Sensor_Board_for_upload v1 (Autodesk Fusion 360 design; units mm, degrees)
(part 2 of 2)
sketch "Sketch7" plane through (-0.0036, 0, 0) normal (-1, 0, 0) x axis (0, -1, 0)
  line L1 (131.7809, -1.8584) -> (65.0417, -1.8584)
  line L2 (135.78, -1.8416) -> (131.7809, -1.8584)
  line L3 (135.7809, 0.1416) -> (135.78, -1.8416)
  line L4 (131.7809, 0.1416) -> (135.7809, 0.1416)
  line L5 (131.7809, 7.5) -> (131.7809, 0.1416)
  line L6 (117.7809, 7.5) -> (131.7809, 7.5)
  line L7 (117.7809, 13.1283) -> (117.7809, 7.5)
  line L8 (110.4051, 13.1776) -> (117.7809, 13.1283)
  line L9 (110.3917, 11.1776) -> (110.4051, 13.1776)
  line L10 (115.7809, 11.1416) -> (110.3917, 11.1776)
  line L11 (115.7809, 5.5) -> (115.7809, 11.1416)
  line L12 (129.7809, 5.5) -> (115.7809, 5.5)
  line L13 (129.7809, 0.1416) -> (129.7809, 5.5)
  line L14 (71.0417, 0.1416) -> (129.7809, 0.1416)
  line L15 (71.0417, 10) -> (71.0417, 0.1416)
  line L16 (88.9317, 10.0211) -> (71.0417, 10)
  line L17 (88.9293, 12.0211) -> (88.9317, 10.0211)
  line L18 (69.0417, 11.9976) -> (88.9293, 12.0211)
  line L19 (69.0417, 0.319) -> (69.0417, 11.9976)
  line L20 (65.0417, 0.319) -> (69.0417, 0.319)
  line L21 (65.0417, -1.8584) -> (65.0417, 0.319)
  line L22 (65.0417, -1.8584) -> (135.78, -1.8416)
  line L23 (69.0417, 0.319) -> (65.0417, 0.319)
  line L24 (131.7809, 11.9976) -> (69.0417, 11.9976)
  line L25 (131.7809, 0.1416) -> (131.7809, 11.9976)
  line L26 (69.0417, 0.1416) -> (131.7809, 0.1416)
  line L27 (69.0417, 11.9976) -> (69.0417, 0.1416)
  point P4 (135.78, -1.8416)
  point P23 (135.78, -1.8416)
  point P2 (65.0417, -1.8584)
  point P24 (65.0417, -1.8584)
  point P22 (65.0417, 0.319)
  point P25 (65.0417, 0.319)
  point P21 (69.0417, 0.319)
  point P26 (69.0417, 0.319)
  point P6 (131.7809, 0.1416)
  point P29 (131.7809, 0.1416)
  point P20 (69.0417, 11.9976)
  point P27 (69.0417, 11.9976)
  coincident P4 P23
  coincident P2 P24
  coincident P22 P25
  coincident P21 P26
  horizontal L24
  vertical L25
  horizontal L26
  vertical L27
  coincident P6 P29
  coincident P20 P27
extrude "Extrude8" new body sketch "Sketch7" profile of L5 L6 L7 L9 L10 L11 L12 L13 L14 L15 L16 L17 L19 L24 L25 L26 L27 along normal blind 2
extrude "Extrude9" new body of existing geometry blind 2
extrude "Extrude10" new body of existing geometry blind 2
position "Position2"
extrude "Extrude11" new body of existing geometry blind 2
extrude "Extrude12" new body of existing geometry blind 2
extrude "Extrude13" new body of existing geometry blind 2
combine "Combine2"
extrude "Extrude14" new body of existing geometry to an object bodies "Left_lid"
combine "Combine3"
sketch "Sketch8" plane through (45.9964, 0, 0) normal (1, 0, 0) x axis (0, 1, 0)
  line L1 (-99.0604, 13.5068) -> (-99.0604, 12.0068)
  line L2 (-102.3675, 13.5022) -> (-99.0604, 13.5068)
  line L3 (-95.2322, 22.0057) -> (-102.3675, 13.5022)
  line L4 (-90.4314, 22.0057) -> (-95.2322, 22.0057)
  line L5 (-90.4296, 13.519) -> (-90.4314, 22.0057)
  line L6 (-90.4296, 10.0045) -> (-90.4296, 13.519)
  line L7 (-88.9317, 10) -> (-90.4296, 10.0045)
  line L8 (-88.9317, 11.9976) -> (-88.9317, 10)
  line L9 (-88.9374, 11.9976) -> (-88.9317, 11.9976)
  line L10 (-88.9374, 12.0211) -> (-88.9374, 11.9976)
  line L11 (-88.9317, 12.0211) -> (-88.9374, 12.0211)
  line L12 (-88.9317, 23.5057) -> (-88.9317, 12.0211)
  line L13 (-95.9317, 23.5057) -> (-88.9317, 23.5057)
  line L14 (-104.6394, 13.1283) -> (-95.9317, 23.5057)
  line L15 (-110.3917, 13.1283) -> (-104.6394, 13.1283)
  line L16 (-110.3917, 11.1776) -> (-110.3917, 13.1283)
  line L17 (-110.4051, 11.1776) -> (-110.3917, 11.1776)
  line L18 (-110.4051, 13.1283) -> (-110.4051, 11.1776)
  line L19 (-117.7809, 13.1283) -> (-110.4051, 13.1283)
  line L20 (-117.7809, 7.5) -> (-117.7809, 13.1283)
  line L21 (-131.7809, 7.5) -> (-117.7809, 7.5)
  line L22 (-131.7809, 0.1416) -> (-131.7809, 7.5)
  line L23 (-135.7809, 0.1416) -> (-131.7809, 0.1416)
  line L24 (-135.78, -1.8416) -> (-135.7809, 0.1416)
  line L25 (-131.7809, -1.8584) -> (-135.78, -1.8416)
  line L26 (-65.0417, -1.8584) -> (-131.7809, -1.8584)
  line L27 (-65.0417, 0.319) -> (-65.0417, -1.8584)
  line L28 (-69.0417, 0.319) -> (-65.0417, 0.319)
  line L29 (-69.0417, 11.9976) -> (-69.0417, 0.319)
  line L30 (-88.9293, 11.9976) -> (-69.0417, 11.9976)
  line L31 (-88.9317, 10.0211) -> (-88.9293, 11.9976)
  line L32 (-71.0417, 10) -> (-88.9317, 10.0211)
  line L33 (-71.0417, 0.1416) -> (-71.0417, 10)
  line L34 (-129.7809, 0.1416) -> (-71.0417, 0.1416)
  line L35 (-129.7809, 5.5) -> (-129.7809, 0.1416)
  line L36 (-115.7809, 5.5) -> (-129.7809, 5.5)
  line L37 (-115.7809, 8.2745) -> (-115.7809, 5.5)
  line L38 (-99.0604, 8.2745) -> (-115.7809, 8.2745)
  line L39 (-99.0604, 11.9976) -> (-99.0604, 8.2745)
  line L40 (-105.5881, 11.9976) -> (-99.0604, 11.9976)
  line L41 (-99.0604, 12.0068) -> (-105.5881, 11.9976)
  line L42 (-95.9317, 23.5057) -> (-104.6394, 13.1283)
  line L43 (-88.9293, 11.9976) -> (-88.9317, 23.5057)
  line L44 (-69.0417, 0.319) -> (-69.0417, 11.9976)
  line L45 (-69.0417, -1.8584) -> (-69.0417, 0.319)
  line L46 (-131.7809, 7.5) -> (-131.7809, -1.8584)
  line L47 (-117.7809, 13.1283) -> (-117.7809, 7.5)
  line L48 (-125.7809, 7.5) -> (-131.7809, 7.5)
  line L49 (-125.7809, -1.8584) -> (-125.7809, 7.5)
  line L50 (-131.7809, -1.8584) -> (-125.7809, -1.8584)
  line L51 (-131.7809, 7.5) -> (-131.7809, -1.8584)
  line L52 (-117.7809, 7.5) -> (-131.7809, 7.5)
  line L53 (-117.7809, 9.5) -> (-117.7809, 7.5)
  line L54 (-131.7809, 9.5) -> (-117.7809, 9.5)
  line L55 (-131.7809, 7.5) -> (-131.7809, 9.5)
  line L56 (-69, 11.9976) -> (-88.9293, 11.9976)
  line L57 (-69, 14) -> (-69, 11.9976)
  line L58 (-88.9293, 14) -> (-69, 14)
  line L59 (-88.9293, 11.9976) -> (-88.9293, 14)
  line L60 (-88.9317, 10) -> (-99.0604, 10.1361)
  circle C1 centre (-114.9874, 10.6426) radius 1
  point P17 (-104.6394, 13.1283)
  point P44 (-104.6394, 13.1283)
  point P16 (-95.9317, 23.5057)
  point P45 (-95.9317, 23.5057)
  point P15 (-88.9317, 23.5057)
  point P46 (-88.9317, 23.5057)
  point P33 (-88.9293, 11.9976)
  point P47 (-88.9293, 11.9976)
  point P32 (-69.0417, 11.9976)
  point P48 (-69.0417, 11.9976)
  point P31 (-69.0417, 0.319)
  point P49 (-69.0417, 0.319)
  point P50 (-69.0417, -1.8584)
  point P28 (-131.7809, -1.8584)
  point P51 (-131.7809, -1.8584)
  point P24 (-131.7809, 7.5)
  point P52 (-131.7809, 7.5)
  point P23 (-117.7809, 7.5)
  point P53 (-117.7809, 7.5)
  point P22 (-117.7809, 13.1283)
  point P54 (-117.7809, 13.1283)
  point P56 (-125.7809, -1.8584)
  point P64 (-99.0604, 10.1361)
  point P10 (-88.9317, 10)
  point P65 (-88.9317, 10)
  point P55 (-125.7809, 7.5)
  point P60 (-131.7809, 9.5)
  coincident P17 P44
  coincident P16 P45
  coincident P15 P46
  coincident P33 P47
  coincident P32 P48
  coincident P31 P49
  coincident L26 P50
  perpendicular L26 L45
  coincident P28 P51
  coincident P24 P52
  coincident P23 P53
  coincident P22 P54
  horizontal L48
  vertical L49
  horizontal L50
  vertical L51
  coincident L26 P56
  horizontal L52
  vertical L53
  horizontal L54
  vertical L55
  horizontal L56
  vertical L57
  horizontal L58
  vertical L59
  midpoint L39 P64
  coincident P10 P65
  dimension "d233" distance P52 P55 = 6
  dimension "d234" distance P52 P60 = 2
extrude "Extrude15" new body sketch "Sketch8" profile of C1 L1 L2 L3 L4 L5 L6 L8 L9 L10 L11 L12 L13 L14 L15 L16 L17 L18 L19 L20 L21 L22 L26 L29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 along normal blind 2 bodies "Right_lid"
extrude "Extrude16" new body sketch "Sketch8" profile of L30 L56 L57 L58 L59 against normal blind 2
extrude "Extrude17" add of existing geometry blind 2
extrude "Extrude18" new body of existing geometry blind 2
extrude "Extrude19" add of existing geometry blind 2
extrude "Extrude20" add of existing geometry blind 6
extrude "Extrude21" add of existing geometry blind 2
extrude "Extrude22" add of existing geometry to an object
extrude "Extrude23" add of existing geometry blind 0.775
remove_body "RemoveBody1"
remove_body "RemoveBody2"
remove_instance "RemoveInstance1"
remove_instance "RemoveInstance1"
remove_instance "RemoveInstance2"
remove_instance "RemoveInstance3"
remove_instance "RemoveInstance4"
remove_instance "RemoveInstance5"
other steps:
extrude "Extrude1" cut sketch "Sketch7" profile of L1 L2 L3 L4 L11 L12 L10 L9 against normal blind 11
extrude "Extrude1" cut sketch "Sketch7" profile of L1 L2 L3 L4 L11 L12 L10 L9 against normal blind 11
extrude "Extrude1" cut sketch "Sketch1" profile of L4 C1 C2 C3 L8 L17 L29 L30 L31 L32 along normal blind 10
extrude "Extrude1" cut sketch "Sketch1" profile of L4 C1 C2 C3 L8 L17 L29 L30 L31 L32 along normal blind 10
extrude "Extrude1" cut sketch "Sketch1" profile of L4 C1 C2 C3 L8 L17 L29 L30 L31 L32 along normal blind 10
extrude "Extrude1" cut sketch "Sketch1" profile of L4 C1 C2 C3 L8 L17 L29 L30 L31 L32 along normal blind 10
extrude "Extrude1" cut sketch "Sketch7" profile of L1 L2 L3 L4 L11 L12 L10 L9 against normal blind 11
extrude "Extrude1" cut sketch "Sketch7" profile of L1 L2 L3 L4 L11 L12 L10 L9 against normal blind 11
extrude "Extrude1" cut sketch "Sketch1" profile of L4 C1 C2 C3 L8 L17 L29 L30 L31 L32 along normal blind 10
extrude "Extrude2" cut sketch "Sketch1" profile of L4 C1 C2 C3 L8 L17 L29 L30 L31 L32 along normal blind 10
extrude "Extrude2" cut sketch "Sketch1" profile of L4 C1 C2 C3 L8 L17 L29 L30 L31 L32 along normal blind 10
extrude "Extrude2" cut sketch "Sketch1" profile of L4 C1 C2 C3 L8 L17 L29 L30 L31 L32 along normal blind 10
extrude "Extrude2" cut sketch "Sketch1" profile of L4 C1 C2 C3 L8 L17 L29 L30 L31 L32 along normal blind 10
extrude "Extrude2" cut sketch "Sketch1" profile of L4 C1 C2 C3 L8 L17 L29 L30 L31 L32 along normal blind 10
extrude "Extrude1" cut sketch "Sketch7" profile of L1 L2 L3 L4 L11 L12 L10 L9 against normal blind 11
extrude "Extrude12" cut sketch "Sketch1" profile of L4 C1 C2 C3 L8 L17 L29 L30 L31 L32 along normal blind 12.5
extrude "Extrude28" cut sketch "Sketch7" profile of L1 L2 L3 L4 L11 L12 L10 L9 against normal blind 11
create_component "CreateComponent1"
create_component "CreateComponent1"
create_component "CreateComponent2"
create_component "CreateComponent2"
create_component "CreateComponent1"
create_component "CreateComponent2"
create_component "CreateComponent3"
create_component "CreateComponent4"
create_component "CreateComponent1"
create_component "CreateComponent2"
create_component "CreateComponent3" sketch "Sketch7"
create_component "CreateComponent4"
create_component "CreateComponent1" sketch "Sketch7"
create_component "CreateComponent2"
create_component "CreateComponent3"
create_component "CreateComponent4"
create_component "CreateComponent5"
create_component "CreateComponent6"
create_component "CreateComponent7"
create_component "CreateComponent8"
create_component "CreateComponent9"
create_component "CreateComponent10"
create_component "CreateComponent11"
create_component "CreateComponent12" sketch "Sketch7"
create_component "CreateComponent13" sketch "Sketch7"
create_component "CreateComponent3" sketch "Sketch7"
create_component "CreateComponent4"
create_component "CreateComponent5"
create_component "CreateComponent1" sketch "Sketch2"
named bodies: "Case", "Left_lid", "Right_lid"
